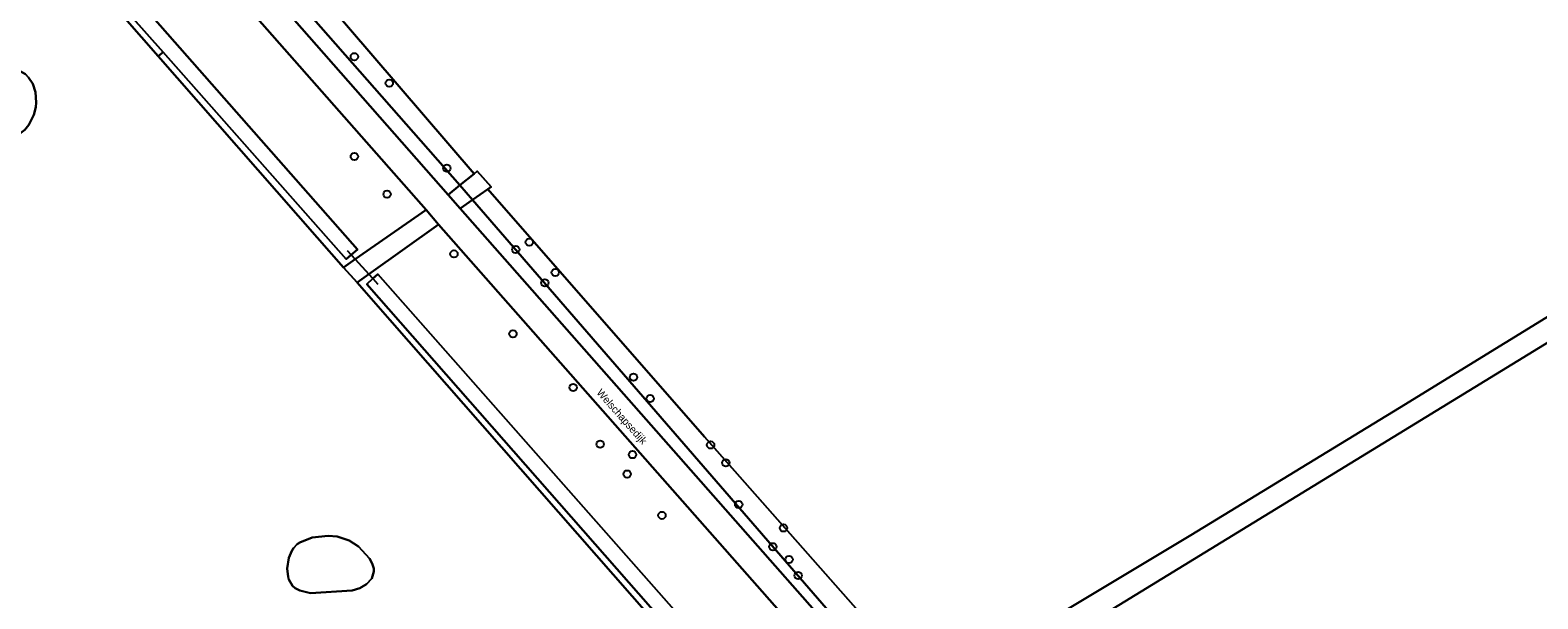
# Model space of a CAD drawing. Extents: x 156061 to 157804, y 383437 to 385640.
# Drawn here: x 157109.2 to 157310.1, y 384338.4 to 384414.3 of the extents above; entities that cross this region are included whole.
import ezdxf

# ---------------------------------------------------------------- set-up
doc = ezdxf.new("R2010")
doc.units = 0
for name, color, linetype in [('IMGEO_Berm_groen', 7, 'Continuous'), ('IMGEO_Boom', 7, 'Continuous'), ('IMGEO_Duiker', 7, 'Continuous'), ('IMGEO_Fietspad_gesloten', 7, 'Continuous'), ('IMGEO_Groenvoorziening', 7, 'Continuous'), ('IMGEO_Hek', 7, 'Continuous'), ('IMGEO_Openbare_ruimte_label', 7, 'Continuous'), ('IMGEO_Rijbaan_lokaal_open', 7, 'Continuous'), ('IMGEO_Terreindeel_zand', 7, 'Continuous'), ('IMGEO_Voetpad_open', 7, 'Continuous'), ('IMGEO_Waterloop', 7, 'Continuous')]:
    doc.layers.add(name, color=color, linetype=linetype)

msp = doc.modelspace()

# ---------------------------------------------------------------- linework, layer by layer
at = {"layer": 'IMGEO_Berm_groen'}
for points in [[(157065.54, 384500), (157058.63, 384507.87), (157045.77, 384503.22), (157048.52, 384500), (157052.19, 384495.7), (157059.52, 384487.13), (157065.57, 384480.04), (157126.23, 384410.84), (157126.88, 384411.37), (157120.35, 384418.76), (157086.06, 384458.08), (157049.71, 384499.29), (157050.54, 384500), (157051.19, 384500.56), (157051.68, 384500), (157128.47, 384412.7), (157152.8, 384385.04), (157151.97, 384384.34), (157152.51, 384383.74), (157161.96, 384390.33), (157136.46, 384419.32)], [(157140.77, 384422.89), (157139.19, 384421.58), (157164.88, 384392.32), (157166.46, 384393.61)]]:
    msp.add_lwpolyline(points, close=True, dxfattribs=at)
for points in [[(157236.85, 384312.33), (157218.46, 384333.49), (157218.41, 384333.56), (157168.13, 384391.67), (157166.48, 384390.53), (157253.43, 384291.77), (157290.16, 384250), (157332.28, 384202.11)], [(157313.49, 384218.11), (157285.45, 384250), (157250.85, 384289.34), (157163.6, 384388.4), (157154.3, 384381.75), (157154.84, 384381.16), (157155.5, 384381.77), (157245.11, 384280.12), (157271.96, 384250), (157283.55, 384237)]]:
    msp.add_lwpolyline(points, dxfattribs=at)
at = {"layer": 'IMGEO_Boom'}
for centre in [(157152.38, 384410.77), (157157.04, 384407.24), (157152.38, 384397.45), (157164.7, 384395.9), (157156.74, 384392.43), (157175.7, 384386.02), (157165.66, 384384.45), (157173.89, 384385.05), (157179.16, 384381.97), (157177.77, 384380.6), (157173.52, 384373.8), (157189.58, 384368), (157181.54, 384366.62), (157191.8, 384365.15), (157185.14, 384359.08), (157189.46, 384357.67), (157199.87, 384358.96), (157201.89, 384356.59), (157188.75, 384355.09), (157193.38, 384349.57), (157203.61, 384351.02), (157209.59, 384347.89), (157208.17, 384345.39), (157210.32, 384343.68), (157211.53, 384341.55)]:
    msp.add_circle(centre, 0.489, dxfattribs=at)
at = {"layer": 'IMGEO_Duiker'}
msp.add_lwpolyline([(157151.44, 384384.92), (157151.97, 384384.34), (157152.51, 384383.74), (157154.3, 384381.75), (157154.84, 384381.16), (157155.5, 384380.42)], dxfattribs=at)
at = {"layer": 'IMGEO_Fietspad_gesloten'}
for points in [[(156945.58, 384638.24), (156948.92, 384634.34), (156956.8, 384625), (156966.54, 384613.57), (156977.24, 384601.18), (156992.9, 384582.99), (157000, 384574.89), (157056.89, 384509.94), (157058.63, 384507.87), (157065.54, 384500), (157136.46, 384419.32), (157161.96, 384390.33), (157163.6, 384388.4), (157250.85, 384289.34), (157285.45, 384250), (157313.49, 384218.11)], [(157316.61, 384214.17), (157320.85, 384207.79), (157322.49, 384205.56), (157328.46, 384198.78), (157332.28, 384202.11), (157290.16, 384250), (157253.43, 384291.77), (157166.48, 384390.53), (157164.88, 384392.32), (157139.19, 384421.58)]]:
    msp.add_lwpolyline(points, dxfattribs=at)
at = {"layer": 'IMGEO_Groenvoorziening'}
for points in [[(157148.09, 384418.78), (157146.56, 384417.25), (157142.5, 384421.89), (157095.54, 384475.47), (157095.31, 384478.28), (157092.8, 384479.33), (157065.35, 384511.67), (157063.61, 384510.46), (157072.83, 384500), (157140.77, 384422.89), (157166.46, 384393.61), (157168.34, 384395.15)], [(157126.23, 384410.84), (157147.44, 384386.65), (157150.95, 384382.65), (157152.51, 384383.74), (157151.97, 384384.34), (157151.27, 384383.76), (157126.88, 384411.37)], [(157097.17, 384399.62), (157096.52, 384400.41), (157096.47, 384401.62), (157096.64, 384402.24), (157097.11, 384403.21), (157097.99, 384404.35), (157100.66, 384406.4), (157105.82, 384408.98), (157106.79, 384409.16), (157107.34, 384409.11), (157108.53, 384408.44), (157108.96, 384408.01), (157109.52, 384407.14), (157109.87, 384406.02), (157109.99, 384404.66), (157109.93, 384404.03), (157109.66, 384403.02), (157108.99, 384401.68), (157108.47, 384401.03), (157105.47, 384398.76), (157105.06, 384398.58), (157104.25, 384398.35), (157103.4, 384398.28), (157097.62, 384399.39)], [(157146.55, 384339.19), (157145.12, 384339.53), (157144.48, 384339.87), (157144.14, 384340.16), (157143.65, 384341.03), (157143.55, 384341.39), (157143.44, 384342.46), (157143.65, 384343.9), (157144.03, 384344.83), (157144.28, 384345.2), (157144.78, 384345.73), (157145.1, 384345.96), (157146.74, 384346.61), (157148.9, 384346.83), (157150.1, 384346.73), (157151.71, 384346.21), (157152.93, 384345.43), (157154.39, 384343.83), (157154.77, 384343.13), (157154.96, 384342.5), (157154.99, 384342.1), (157154.72, 384341.17), (157154.01, 384340.38), (157153.11, 384339.87), (157152.08, 384339.54)]]:
    msp.add_lwpolyline(points, close=True, dxfattribs=at)
for points in [[(157422.9, 384440.97), (157244.99, 384331.9), (157233.07, 384324.81), (157231.44, 384327.44), (157263.86, 384346.91), (157291.7, 384363.94), (157433.08, 384451.02), (157463.89, 384469.64), (157500, 384491.86)], [(157235.49, 384286.21), (157233.65, 384288.31), (157214.42, 384310.24), (157157.1, 384375.67), (157152.75, 384380.64), (157150.95, 384382.65), (157147.44, 384386.65), (157126.23, 384410.84), (157065.57, 384480.04)], [(157148.09, 384418.78), (157168.34, 384395.15), (157168.77, 384395.5), (157170.61, 384393.4), (157170.15, 384393.08), (157199.06, 384360.03), (157296.11, 384250), (157333.07, 384208.04), (157370.06, 384231.22), (157372.73, 384226.9), (157384.48, 384234.26), (157383.56, 384235.74), (157375.77, 384248.22), (157376.17, 384248.48), (157394.08, 384260.05), (157409.63, 384270.1), (157417.93, 384257.27), (157401.72, 384247.12), (157402.65, 384245.64), (157409.61, 384250), (157420.5, 384257)], [(157338.54, 384205.49), (157340.57, 384206.76), (157372.73, 384226.9), (157370.06, 384231.22), (157333.07, 384208.04), (157296.11, 384250), (157199.06, 384360.03), (157170.15, 384393.08), (157168.15, 384391.68), (157168.13, 384391.67), (157218.41, 384333.56)], [(157281.33, 384234.83), (157268.18, 384250), (157243.45, 384278.53), (157154.04, 384380.42), (157154.84, 384381.16), (157154.3, 384381.75), (157152.75, 384380.64), (157157.1, 384375.67), (157214.42, 384310.24), (157233.65, 384288.31), (157235.49, 384286.21), (157267.06, 384250), (157294.3, 384218.6), (157310.23, 384198.96), (157314.94, 384193.15), (157317.96, 384189.64), (157318.6, 384190.2)]]:
    msp.add_lwpolyline(points, dxfattribs=at)
at = {"layer": 'IMGEO_Hek'}
for points in [[(157168.34, 384395.15), (157148.09, 384418.78)], [(157296.11, 384250), (157199.06, 384360.03), (157170.15, 384393.08)]]:
    msp.add_lwpolyline(points, dxfattribs=at)
at = {"layer": 'IMGEO_Rijbaan_lokaal_open'}
msp.add_lwpolyline([(157436.45, 384449.02), (157483.73, 384477.95), (157500, 384488.13), (157519.16, 384500), (157576.02, 384534.59), (157575.65, 384535.14), (157574.2, 384537.32), (157551.17, 384523.14), (157550.12, 384524.27), (157535.92, 384547.39), (157533.05, 384545.65), (157542.26, 384531.48), (157547.06, 384523.53), (157546.9, 384520.27), (157513.14, 384500), (157500, 384491.86), (157463.89, 384469.64), (157433.08, 384451.02), (157291.7, 384363.94), (157263.86, 384346.91), (157231.44, 384327.44), (157233.07, 384324.81), (157244.99, 384331.9), (157422.9, 384440.97)], dxfattribs=at)
at = {"layer": 'IMGEO_Terreindeel_zand'}
for points in [[(157097.99, 384404.35), (157097.11, 384403.21), (157096.64, 384402.24), (157096.47, 384401.62), (157096.52, 384400.41), (157097.17, 384399.62), (157097.62, 384399.39), (157103.4, 384398.28), (157104.25, 384398.35), (157105.06, 384398.58), (157105.47, 384398.76), (157108.47, 384401.03), (157108.99, 384401.68), (157109.66, 384403.02), (157109.93, 384404.03), (157109.99, 384404.66), (157109.87, 384406.02), (157109.52, 384407.14), (157108.96, 384408.01), (157108.53, 384408.44), (157107.34, 384409.11), (157106.79, 384409.16), (157105.82, 384408.98), (157100.66, 384406.4)], [(157146.74, 384346.61), (157145.1, 384345.96), (157144.78, 384345.73), (157144.28, 384345.2), (157144.03, 384344.83), (157143.65, 384343.9), (157143.44, 384342.46), (157143.55, 384341.39), (157143.65, 384341.03), (157144.14, 384340.16), (157144.48, 384339.87), (157145.12, 384339.53), (157146.55, 384339.19), (157152.08, 384339.54), (157153.11, 384339.87), (157154.01, 384340.38), (157154.72, 384341.17), (157154.99, 384342.1), (157154.96, 384342.5), (157154.77, 384343.13), (157154.39, 384343.83), (157152.93, 384345.43), (157151.71, 384346.21), (157150.1, 384346.73), (157148.9, 384346.83)]]:
    msp.add_lwpolyline(points, close=True, dxfattribs=at)
at = {"layer": 'IMGEO_Voetpad_open'}
for points in [[(157168.15, 384391.68), (157170.15, 384393.08), (157170.61, 384393.4), (157168.77, 384395.5), (157168.34, 384395.15), (157166.46, 384393.61), (157168.13, 384391.67)], [(157166.46, 384393.61), (157164.88, 384392.32), (157166.48, 384390.53), (157168.13, 384391.67)], [(157163.6, 384388.4), (157161.96, 384390.33), (157152.51, 384383.74), (157150.95, 384382.65), (157152.75, 384380.64), (157154.3, 384381.75)]]:
    msp.add_lwpolyline(points, close=True, dxfattribs=at)
at = {"layer": 'IMGEO_Waterloop'}
msp.add_lwpolyline([(157051.68, 384500), (157051.19, 384500.56), (157050.54, 384500), (157049.71, 384499.29), (157086.06, 384458.08), (157120.35, 384418.76), (157126.88, 384411.37), (157151.27, 384383.76), (157151.97, 384384.34), (157152.8, 384385.04), (157128.47, 384412.7)], close=True, dxfattribs=at)
for points in [[(157155.5, 384381.77), (157154.84, 384381.16), (157154.04, 384380.42), (157243.45, 384278.53), (157268.18, 384250), (157281.33, 384234.83)], [(157283.55, 384237), (157271.96, 384250), (157245.11, 384280.12), (157155.5, 384381.77)]]:
    msp.add_lwpolyline(points, dxfattribs=at)

# ---------------------------------------------------------------- texts
at = {"layer": 'IMGEO_Openbare_ruimte_label'}
msp.add_text('Welschapsedijk', height=1, rotation=311.5146, dxfattribs=at).set_placement((157184.59, 384365.89))

doc.saveas('drawing.dxf')
